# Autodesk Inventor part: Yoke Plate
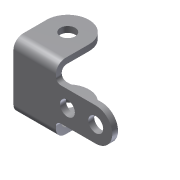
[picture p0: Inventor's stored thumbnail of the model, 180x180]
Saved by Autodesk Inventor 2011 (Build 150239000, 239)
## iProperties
Created: 2010-03
Part Number: Yoke Plate
Document SubType Name: Modeling
Designer: bhakira
Density: 1 g/cm^3
Author: bhakira
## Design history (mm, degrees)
sketch "Sketch1"
  geometry: L1 (28.578, 36.513)-(28.483, -7.913); L2 (-28.517, -7.961)-(28.483, -7.913); L3 (-28.554, 36.476)-(-28.517, -7.961); C1 r 10 at (0.012, 36.5); A1 r 28.566 centre (0.012, 36.5) between (28.578, 36.513) and (-28.554, 36.476); 1 further point
  constraints: 6 end point, 2 centre point, 2 point on circle, 1 coincident, 1 perpendicular, 1 tangent, 1 other
  dimensions: "d8" = 57 distance of L2.start L1.end; "d9" = 36.5 distance of point (0, 0) C1.centre; "d10" = 28.5 distance from line of L1 point (0, 0); "d11" = 20 diameter of C1
extrude "Extrusion1" new body sketch "Sketch1" stored distance "d12" = 89; taper "d13" = 0 deg
sketch "Sketch2"
  geometry: L1 (8, 73.001)-(8, 7.914); L2 (8, 7.914)-(81, 7.914); L3 (81, 7.914)-(81, 73.001); L4 (8, 73.001)-(81, 73.001); 2 further points
  constraints: 8 end point, 1 perpendicular
  dimensions: "d14" = 73 distance of L1.start L3.end; "d17" = 8 distance from line of point (89, 44.426) L3
extrude "Extrusion2" cut sketch "Sketch2" stored distance "d18" = 88.9; taper "d19" = 0 deg
sketch "Sketch3"
  geometry: L1 (0, 73)-(0, 0) reference; L2 (0, 58.725)-(53.5, 58.725); L3 (53.5, 14.225)-(0, 14.225); L4 (0, 14.225)-(0, 58.725); C1 r 10 at (53.5, 36.475); C2 r 10 at (15.5, 36.513); A1 r 22.25 centre (53.5, 36.475) between (53.5, 14.225) and (53.5, 58.725); 1 further point
  constraints: 6 end point, 3 centre point, 2 point on circle, 1 coincident, 1 equal radius, 1 horizontal, 1 parallel, 1 point on line, 1 tangent
  dimensions: "d23" = 44.5 diameter of A1; "d24" = 44.5 distance between parallel lines of L3 L2; "d25" = 22.225 distance from line of point (-28.5, 36.5) L2; "d26" = 20 diameter of C1; "d27" = 38 distance of A1.centre C2.centre; "d28" = 15.5 distance from line of L1 C2.centre
extrude "Extrusion3" join sketch "Sketch3" stored distance "d29" = 88.9; taper "d30" = 0 deg
fillet "Fillet1" dims "d31" = 12.7
fillet "Fillet2" dims "d32" = 6.35
fillet "Fillet3" dims "d33" = 6.35
body "Solid1"
